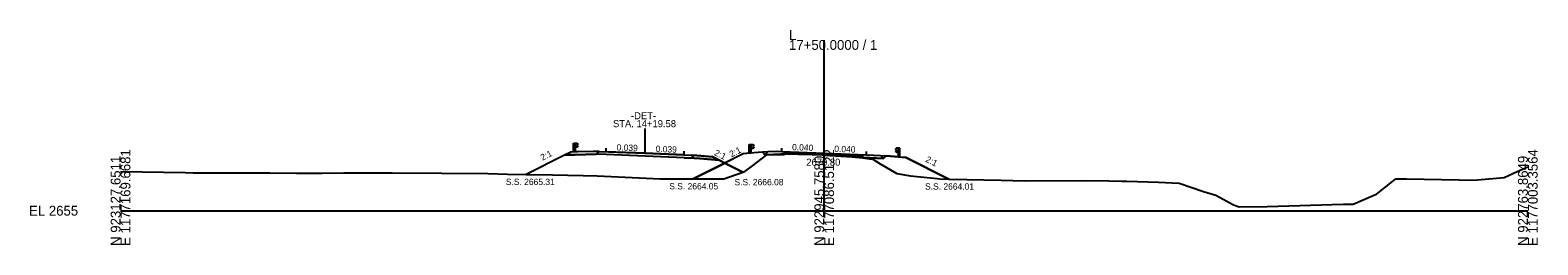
# Model space of a CAD drawing. Extents: x -26 to 1403, y -10 to 9563.
# Drawn here: x -25.7 to 402.8, y 7490.3 to 7551.3 of the extents above; entities that cross this region are included whole.
import ezdxf

# ---------------------------------------------------------------- set-up
doc = ezdxf.new("R2010")
doc.units = 0
for name, color, linetype in [('Exist Cross Section Cell', 7, 'Continuous'), ('Exist XS Center Line Elevation Label', 7, 'Continuous'), ('Exist XS Ground Line', 7, 'Continuous'), ('Prop XS Ditch Slope Text', 7, 'Continuous'), ('Prop XS Dump Level', 7, 'Continuous'), ('Prop XS Earthwork Shape', 7, 'Continuous'), ('Prop XS EOT Tick Mark', 7, 'Continuous'), ('Prop XS Finish Grade', 7, 'Continuous'), ('Prop XS Finish Grade Earthwork', 7, 'Continuous'), ('Prop XS Finish Grade Paved Shoulder', 7, 'Continuous'), ('Prop XS Finish Grade Pavement', 7, 'Continuous'), ('Prop XS Guardrail', 7, 'Continuous'), ('Prop XS Pvmt Edge Slope', 7, 'Continuous'), ('Prop XS SE Text', 7, 'Continuous'), ('Prop XS Shoulder Borrow Shape', 7, 'Continuous'), ('Prop XS Side Slope Text', 7, 'Continuous'), ('Prop XS SS Elevation Text', 7, 'Continuous'), ('Prop XS Subgrade Earthwork', 7, 'Continuous'), ('Prop XS Vertical Lines', 7, 'Continuous'), ('Prop XS Wedging', 7, 'Continuous')]:
    doc.layers.add(name, color=color, linetype=linetype)

msp = doc.modelspace()

# ---------------------------------------------------------------- linework, layer by layer
at = {"layer": 'Exist Cross Section Cell'}
for p, q in [((200, 7500), (200, 7548.51)), ((0, 7500), (200, 7500)), ((200, 7500), (400, 7500))]:
    msp.add_line(p, q, dxfattribs=at)
at = {"layer": 'Exist XS Ground Line'}
for p, q in [((177.42, 7511.17), (179.61, 7512.76)), ((179.61, 7512.76), (183.65, 7515.84)), ((183.65, 7515.84), (186.35, 7515.98)), ((186.35, 7515.98), (188.73, 7516.17)), ((188.73, 7516.17), (196.55, 7515.93)), ((196.55, 7515.93), (199.39, 7515.84)), ((199.39, 7515.84), (200, 7515.8)), ((200, 7515.8), (207.91, 7515.27)), ((207.91, 7515.27), (210.88, 7515.06)), ((210.88, 7515.06), (212.87, 7514.78)), ((212.87, 7514.78), (213.81, 7514.66)), ((213.81, 7514.66), (215.93, 7513.32)), ((215.93, 7513.32), (220.64, 7510.55)), ((396.92, 7511.15), (400, 7512.49)), ((0, 7511.1), (18.34, 7510.83)), ((18.34, 7510.83), (20.67, 7510.78)), ((20.67, 7510.78), (21.99, 7510.77)), ((21.99, 7510.77), (22.5, 7510.77)), ((22.5, 7510.77), (35.96, 7510.74)), ((35.96, 7510.74), (42.42, 7510.78)), ((42.42, 7510.78), (50.01, 7510.67)), ((50.01, 7510.67), (57.28, 7510.71)), ((57.28, 7510.71), (63.45, 7510.78)), ((63.45, 7510.78), (77.23, 7510.81)), ((77.23, 7510.81), (91.34, 7510.71)), ((91.34, 7510.71), (104.37, 7510.57)), ((104.37, 7510.57), (110.01, 7510.4)), ((110.01, 7510.4), (122.79, 7510.2)), ((122.79, 7510.2), (131.49, 7510.01)), ((131.49, 7510.01), (135.46, 7509.88)), ((135.46, 7509.88), (153.35, 7509.04)), ((153.35, 7509.04), (171.45, 7509.06)), ((171.45, 7509.06), (177.42, 7511.17)), ((220.64, 7510.55), (224.54, 7509.92)), ((224.54, 7509.92), (232.13, 7509.16)), ((232.13, 7509.16), (232.91, 7509.04)), ((232.91, 7509.04), (235.61, 7509)), ((235.61, 7509), (250.34, 7508.71)), ((250.34, 7508.71), (256.94, 7508.51)), ((256.94, 7508.51), (273.53, 7508.56)), ((273.53, 7508.56), (280.9, 7508.53)), ((280.9, 7508.53), (284.64, 7508.43)), ((284.64, 7508.43), (286.02, 7508.37)), ((286.02, 7508.37), (295, 7508.08)), ((295, 7508.08), (300.9, 7507.87)), ((357.01, 7504.75), (361.54, 7508.29)), ((361.54, 7508.29), (362.52, 7509.1)), ((362.52, 7509.1), (365.49, 7509.04)), ((365.49, 7509.04), (380.47, 7508.74)), ((380.47, 7508.74), (383.3, 7508.68)), ((383.3, 7508.68), (385.66, 7508.78)), ((385.66, 7508.78), (393.26, 7509.44)), ((393.26, 7509.44), (396.92, 7511.15)), ((300.9, 7507.87), (307.85, 7505.48)), ((307.85, 7505.48), (311.31, 7504.39)), ((311.31, 7504.39), (315.45, 7502.19)), ((350.31, 7501.85), (356.01, 7504.31)), ((356.01, 7504.31), (357.01, 7504.75)), ((315.45, 7502.19), (316.32, 7501.66)), ((316.32, 7501.66), (317.98, 7501.07)), ((317.98, 7501.07), (325.9, 7501.18)), ((325.9, 7501.18), (347.55, 7501.86)), ((347.55, 7501.86), (350.31, 7501.85))]:
    msp.add_line(p, q, dxfattribs=at)
at = {"layer": 'Prop XS Dump Level'}
for p, q in [((136.02, 7516.84), (149.11, 7516.32)), ((149.11, 7516.32), (138.02, 7516.76)), ((188, 7516.82), (200, 7516.35)), ((160.2, 7515.89), (149.11, 7516.32)), ((149.11, 7516.32), (162.2, 7515.81)), ((200, 7516.35), (212, 7515.86))]:
    msp.add_line(p, q, dxfattribs=at)
at = {"layer": 'Prop XS Earthwork Shape'}
for p, q in [((182.43, 7516.62), (180, 7516.43)), ((183.15, 7515.89), (182.43, 7516.62)), ((126.38, 7515.85), (115.31, 7510.32)), ((129.22, 7515.91), (126.38, 7515.85)), ((135.22, 7516.04), (129.22, 7515.91)), ((138.02, 7515.93), (135.22, 7516.04)), ((149.11, 7515.49), (138.02, 7515.93)), ((160.2, 7515.05), (149.11, 7515.49)), ((163.07, 7514.94), (160.2, 7515.05)), ((162.72, 7509.05), (171.75, 7513.56)), ((171.75, 7513.56), (162.73, 7509.05)), ((164.68, 7514.81), (163.07, 7514.94)), ((170.11, 7514.38), (164.68, 7514.81)), ((171.75, 7513.56), (170.11, 7514.38)), ((177, 7516.19), (171.75, 7513.56)), ((176.9, 7510.99), (171.75, 7513.56)), ((171.75, 7513.56), (176.9, 7510.99)), ((177.42, 7511.17), (179.61, 7512.76)), ((179.61, 7512.76), (183.65, 7515.84)), ((185.61, 7515.94), (183.15, 7515.89)), ((183.65, 7515.84), (185.61, 7515.94)), ((216.87, 7514.84), (210.88, 7515.08)), ((210.88, 7515.08), (210.88, 7515.06)), ((210.88, 7515.06), (212.87, 7514.78)), ((212.87, 7514.78), (213.81, 7514.66)), ((213.81, 7514.66), (215.93, 7513.32)), ((215.93, 7513.32), (220.64, 7510.55)), ((217.61, 7515.58), (216.87, 7514.84)), ((220, 7515.39), (217.61, 7515.58)), ((221.04, 7515.3), (220, 7515.39)), ((235.46, 7509.01), (223.22, 7515.13)), ((115.31, 7510.32), (122.79, 7510.2)), ((122.79, 7510.2), (131.49, 7510.01)), ((131.49, 7510.01), (135.46, 7509.88)), ((135.46, 7509.88), (153.35, 7509.04)), ((153.35, 7509.04), (162.72, 7509.05)), ((162.73, 7509.05), (171.45, 7509.06)), ((171.45, 7509.06), (176.9, 7510.99)), ((176.9, 7510.99), (177.42, 7511.17)), ((220.64, 7510.55), (224.54, 7509.92)), ((224.54, 7509.92), (232.13, 7509.16)), ((232.13, 7509.16), (232.91, 7509.04)), ((232.91, 7509.04), (235.46, 7509.01))]:
    msp.add_line(p, q, dxfattribs=at)
for points in [[(180, 7516.43), (179.19, 7516.36), (178.69, 7516.32), (177, 7516.19)], [(223.22, 7515.13), (221.54, 7515.26), (221.04, 7515.3)], [(162.73, 7509.05), (162.73, 7509.05)]]:
    msp.add_lwpolyline(points, dxfattribs=at)
at = {"layer": 'Prop XS EOT Tick Mark'}
for p, q in [((138.02, 7516.76), (138.02, 7517.76)), ((160.2, 7515.89), (160.2, 7516.89)), ((188, 7516.82), (188, 7517.82)), ((212, 7515.86), (212, 7516.86))]:
    msp.add_line(p, q, dxfattribs=at)
at = {"layer": 'Prop XS Finish Grade'}
for p, q in [((136.02, 7516.84), (134.45, 7516.81)), ((184, 7516.74), (182.43, 7516.62)), ((162.2, 7515.81), (163.81, 7515.68)), ((216, 7515.7), (217.61, 7515.58))]:
    msp.add_line(p, q, dxfattribs=at)
at = {"layer": 'Prop XS Finish Grade Earthwork'}
for p, q in [((128.02, 7516.67), (126.38, 7515.85)), ((130.02, 7516.71), (128.02, 7516.67)), ((134.45, 7516.81), (130.02, 7516.71)), ((182.43, 7516.62), (180, 7516.43)), ((126.38, 7515.85), (115.31, 7510.32)), ((177, 7516.19), (162.72, 7509.05)), ((163.81, 7515.68), (168.21, 7515.33)), ((168.21, 7515.33), (170.11, 7514.38)), ((170.11, 7514.38), (176.9, 7510.99)), ((180, 7516.43), (177, 7516.19)), ((217.61, 7515.58), (220, 7515.39)), ((220, 7515.39), (223.22, 7515.13)), ((223.22, 7515.13), (235.46, 7509.01))]:
    msp.add_line(p, q, dxfattribs=at)
at = {"layer": 'Prop XS Finish Grade Paved Shoulder'}
for p, q in [((188, 7516.82), (184, 7516.74)), ((212, 7515.86), (216, 7515.7))]:
    msp.add_line(p, q, dxfattribs=at)
at = {"layer": 'Prop XS Finish Grade Pavement'}
for p, q in [((136.02, 7516.84), (149.11, 7516.32)), ((188, 7516.82), (200, 7516.35)), ((149.11, 7516.32), (162.2, 7515.81)), ((200, 7516.35), (212, 7515.86))]:
    msp.add_line(p, q, dxfattribs=at)
at = {"layer": 'Prop XS Guardrail'}
for p, q in [((128.7, 7519.2), (129.2, 7519.2)), ((128.7, 7516.7), (128.7, 7519.2)), ((129.2, 7519.2), (129.7, 7519.2)), ((129.2, 7519.2), (129.2, 7516.7)), ((129.7, 7518.06), (129.2, 7518.06)), ((129.7, 7519.2), (129.99, 7519)), ((129.99, 7518.88), (129.7, 7518.68)), ((129.7, 7518.68), (129.7, 7518.58)), ((129.7, 7518.58), (129.99, 7518.38)), ((129.99, 7518.26), (129.7, 7518.06)), ((129.99, 7519), (130.02, 7518.94)), ((130.02, 7518.94), (129.99, 7518.88)), ((129.99, 7518.38), (130.02, 7518.32)), ((130.02, 7518.32), (129.99, 7518.26)), ((178.69, 7518.82), (179.19, 7518.82)), ((178.69, 7516.32), (178.69, 7518.82)), ((179.19, 7518.82), (179.69, 7518.82)), ((179.19, 7518.82), (179.19, 7516.32)), ((179.69, 7517.69), (179.19, 7517.69)), ((179.69, 7518.82), (179.98, 7518.62)), ((179.98, 7518.5), (179.69, 7518.3)), ((179.69, 7518.3), (179.69, 7518.21)), ((179.69, 7518.21), (179.98, 7518.01)), ((179.98, 7517.89), (179.69, 7517.69)), ((179.98, 7518.62), (180.01, 7518.56)), ((180.01, 7518.56), (179.98, 7518.5)), ((179.98, 7518.01), (180.01, 7517.95)), ((180.01, 7517.95), (179.98, 7517.89)), ((220.25, 7517.56), (220.22, 7517.5)), ((220.22, 7517.5), (220.25, 7517.44)), ((220.25, 7516.95), (220.22, 7516.89)), ((220.22, 7516.89), (220.25, 7516.83)), ((220.54, 7517.76), (220.25, 7517.56)), ((220.25, 7517.44), (220.54, 7517.24)), ((220.54, 7517.15), (220.25, 7516.95)), ((220.25, 7516.83), (220.54, 7516.63)), ((221.04, 7517.76), (220.54, 7517.76)), ((220.54, 7517.24), (220.54, 7517.15)), ((220.54, 7516.63), (221.04, 7516.63)), ((221.54, 7517.76), (221.04, 7517.76)), ((221.04, 7517.76), (221.04, 7515.26)), ((221.54, 7515.26), (221.54, 7517.76))]:
    msp.add_line(p, q, dxfattribs=at)
at = {"layer": 'Prop XS Pvmt Edge Slope'}
for p, q in [((136.02, 7516.84), (135.22, 7516.04)), ((184, 7516.74), (183.15, 7515.89)), ((162.2, 7515.81), (163.07, 7514.94)), ((216, 7515.7), (216.87, 7514.84))]:
    msp.add_line(p, q, dxfattribs=at)
at = {"layer": 'Prop XS Shoulder Borrow Shape'}
for p, q in [((128.02, 7516.67), (126.38, 7515.85)), ((129.2, 7516.7), (128.02, 7516.67)), ((130.02, 7516.71), (129.2, 7516.7)), ((129.2, 7516.7), (129.2, 7516.7)), ((134.45, 7516.81), (130.02, 7516.71)), ((136.02, 7516.84), (134.45, 7516.81)), ((135.22, 7516.04), (136.02, 7516.84)), ((126.38, 7515.85), (129.22, 7515.91)), ((129.22, 7515.91), (135.22, 7516.04)), ((163.81, 7515.68), (162.2, 7515.81)), ((162.2, 7515.81), (163.07, 7514.94)), ((163.07, 7514.94), (164.68, 7514.81)), ((168.21, 7515.33), (163.81, 7515.68)), ((164.68, 7514.81), (170.11, 7514.38)), ((170.11, 7514.38), (168.21, 7515.33))]:
    msp.add_line(p, q, dxfattribs=at)
msp.add_lwpolyline([(129.2, 7516.7), (129.2, 7516.7)], dxfattribs=at)
at = {"layer": 'Prop XS Subgrade Earthwork'}
for p, q in [((183.15, 7515.89), (182.43, 7516.62)), ((129.22, 7515.91), (126.38, 7515.85)), ((135.22, 7516.04), (129.22, 7515.91)), ((138.02, 7515.93), (135.22, 7516.04)), ((149.11, 7515.49), (138.02, 7515.93)), ((160.2, 7515.05), (149.11, 7515.49)), ((160.2, 7515.05), (163.07, 7514.94)), ((163.07, 7514.94), (164.68, 7514.81)), ((164.68, 7514.81), (170.11, 7514.38)), ((188, 7515.99), (183.15, 7515.89)), ((188, 7515.99), (188.73, 7515.96)), ((188.73, 7515.96), (188.73, 7516.17)), ((210.88, 7515.08), (210.88, 7515.06)), ((210.88, 7515.08), (216.87, 7514.84)), ((216.87, 7514.84), (217.61, 7515.58))]:
    msp.add_line(p, q, dxfattribs=at)
at = {"layer": 'Prop XS Vertical Lines'}
msp.add_line((149.11, 7516.32), (149.11, 7523.32), dxfattribs=at)
at = {"layer": 'Prop XS Wedging'}
for p, q in [((185.61, 7515.94), (188, 7515.99)), ((186.35, 7515.98), (185.61, 7515.94)), ((188.73, 7516.17), (186.35, 7515.98)), ((188, 7515.99), (188.73, 7515.96)), ((188.73, 7515.96), (188.73, 7516.17))]:
    msp.add_line(p, q, dxfattribs=at)
for points in [[(188.73, 7516.17), (188.73, 7516.58), (196.55, 7516.27), (199.39, 7516.16), (200, 7516.13), (200.44, 7516.11), (207.91, 7515.79), (210.88, 7515.67), (210.88, 7515.06), (207.91, 7515.27), (200.44, 7515.77), (200, 7515.8), (199.39, 7515.84), (196.55, 7515.93)], [(188.73, 7516.17), (188.73, 7516.58), (196.55, 7516.27), (199.39, 7516.16), (200, 7516.13), (200.44, 7516.11), (207.91, 7515.79), (210.88, 7515.67), (210.88, 7515.06), (207.91, 7515.27), (200.44, 7515.77), (200, 7515.8), (199.39, 7515.84), (196.55, 7515.93)], [(206.64, 7515.35), (206.87, 7515.59), (207.91, 7515.54), (210.88, 7515.42), (210.88, 7515.06), (207.91, 7515.27)]]:
    msp.add_lwpolyline(points, close=True, dxfattribs=at)

# ---------------------------------------------------------------- texts
at = {"layer": 'Exist Cross Section Cell'}
for s, p in [('L', (190, 7548.51)), ('17+50.0000 / 1', (190, 7545.71)), ('EL 2655', (-26, 7498.6))]:
    msp.add_text(s, height=2.8, dxfattribs=at).set_placement(p)
for s, p in [('E 1177169.6681', (2.8, 7490)), ('E 1177086.5122', (202.8, 7490)), ('E 1177003.3564', (402.8, 7490)), ('N 923127.6511', (0, 7490)), ('N 922945.7580', (200, 7490)), ('N 922763.8649', (400, 7490))]:
    msp.add_text(s, height=2.8, rotation=90, dxfattribs=at).set_placement(p)
at = {"layer": 'Exist XS Center Line Elevation Label'}
msp.add_text('2670.80', height=2, dxfattribs=at).set_placement((194.92, 7512.8))
at = {"layer": 'Prop XS Ditch Slope Text'}
msp.add_text('2:1', height=1.8, rotation=334.2998, dxfattribs=at).set_placement((168.57, 7515.87))
at = {"layer": 'Prop XS Dump Level'}
for s, p in [('Case1', (130.02, 7516.55)), ('Case1', (168.2, 7515.21)), ('Case2', (180, 7516.39)), ('Case2', (220, 7515.35))]:
    msp.add_text(s, height=0.04, dxfattribs=at).set_placement(p)
at = {"layer": 'Prop XS SE Text'}
for s, rotation, p in [('0.039', 357.7506, (140.96, 7517.14)), ('0.039', 357.7518, (152.06, 7516.71)), ('0.040', 357.7094, (190.84, 7517.21)), ('0.040', 357.7094, (202.84, 7516.73))]:
    msp.add_text(s, height=1.8, rotation=rotation, dxfattribs=at).set_placement(p)
at = {"layer": 'Prop XS Side Slope Text'}
for rotation, p in [(26.5651, (119.9, 7514.17)), (26.5651, (173.62, 7515.14)), (333.4349, (228.63, 7514.01))]:
    msp.add_text('2:1', height=1.8, rotation=rotation, dxfattribs=at).set_placement(p)
at = {"layer": 'Prop XS SS Elevation Text'}
for s, p in [('S.S. 2665.31', (109.51, 7507.31)), ('S.S. 2666.08', (174.51, 7507.23)), ('S.S. 2664.05', (155.95, 7506.05)), ('S.S. 2664.01', (228.67, 7506))]:
    msp.add_text(s, height=1.8, dxfattribs=at).set_placement(p)
at = {"layer": 'Prop XS Vertical Lines'}
for s, p in [('STA. 14+19.58', (139.97, 7523.74)), ('-DET-', (145.09, 7525.99))]:
    msp.add_text(s, height=2, dxfattribs=at).set_placement(p)

doc.saveas('drawing.dxf')
